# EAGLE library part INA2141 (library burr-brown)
Instrumentation Amplifier Dual, Low Power, G = 10, 100
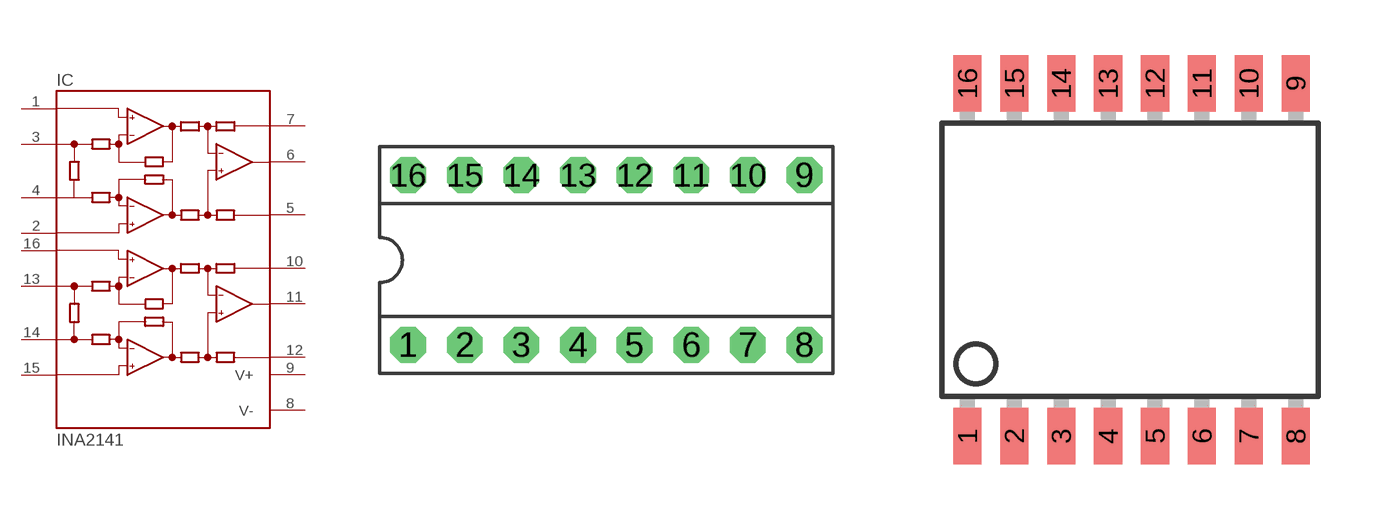
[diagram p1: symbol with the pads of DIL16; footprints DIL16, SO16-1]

Designator prefix IC

## INA2141P (OC_FARNELL: unknown; OC_NEWARK: unknown)  [DIL16]
1  INA-  in
2  INA+  in
3  JA  pas
4  JA  pas
5  REFA  in
6  VOA  out
7  SENSEA  in
8  V-  pwr
9  V+  pwr
10  SENSEB  in
11  VOB  out
12  REFB  in
13  JB  pas
14  JB  pas
15  INB+  in
16  INB-  in

## INA2141U (MF: TEXAS INSTRUMENT CONNECTORS; MPN: INA2141U; OC_FARNELL: 1459468; OC_NEWARK: 74C9853)  [SO16-1]
Pads as for DIL16

## Footprint DIL16 (pad centres in mm)
Dual In Line
drill 0.813 pad 1.6 octagon: 1 -8.89,-3.81; 2 -6.35,-3.81; 3 -3.81,-3.81; 4 -1.27,-3.81; 5 1.27,-3.81; 6 3.81,-3.81; 7 6.35,-3.81; 8 8.89,-3.81; 9 8.89,3.81; 10 6.35,3.81; 11 3.81,3.81; 12 1.27,3.81; 13 -1.27,3.81; 14 -3.81,3.81; 15 -6.35,3.81; 16 -8.89,3.81

## Footprint SO16-1 (pad centres in mm)
Small Outline Package
smd 0.762 x 1.524: 1 -4.445,-4.775; 2 -3.175,-4.775; 3 -1.905,-4.775; 4 -0.635,-4.775; 5 0.635,-4.775; 6 1.905,-4.775; 7 3.175,-4.775; 8 4.445,-4.775; 9 4.445,4.775; 10 3.175,4.775; 11 1.905,4.775; 12 0.635,4.775; 13 -0.635,4.775; 14 -1.905,4.775; 15 -3.175,4.775; 16 -4.445,4.775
